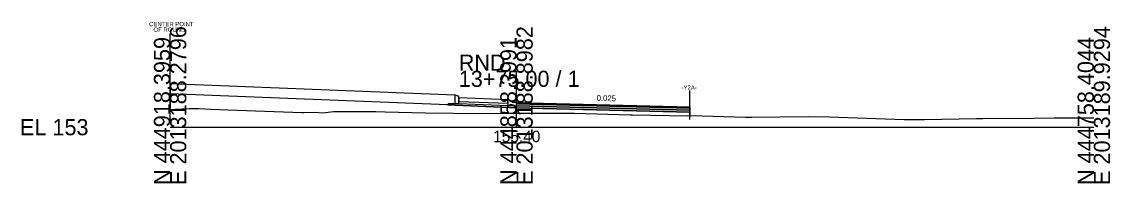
# Model space of a CAD drawing. Extents: x -26 to 163, y -10 to 7518.
# Drawn here: x -25.7 to 162.8, y 7490.3 to 7518.2 of the extents above; entities that cross this region are included whole.
import ezdxf

# ---------------------------------------------------------------- set-up
doc = ezdxf.new("R2010")
doc.units = 0
for name, color, linetype in [('Exist Cross Section Cell', 7, 'Continuous'), ('Exist XS Center Line Elevation Label', 7, 'Continuous'), ('Exist XS Ground Line', 7, 'Continuous'), ('Prop CMT Conc Surface', 7, 'Continuous'), ('Prop CMT Concrete Structures', 7, 'Continuous'), ('Prop CMT Pvmt Course 1', 7, 'Continuous'), ('Prop CMT Pvmt Course 1 CG', 7, 'Continuous'), ('Prop CMT Pvmt Course 2', 7, 'Continuous'), ('Prop CMT Pvmt Course 3', 7, 'Continuous'), ('Prop CMT Pvmt Surface', 7, 'Continuous'), ('Prop CMT Shear Line', 7, 'Continuous'), ('Prop CMT Shear Line Text', 7, 'Continuous'), ('Prop CMT Slope Grass', 7, 'Continuous'), ('Prop CMT Subgrade Earthwork', 7, 'Continuous'), ('Prop XS Earthwork Shape', 7, 'Continuous'), ('Prop XS SE Text', 7, 'Continuous')]:
    doc.layers.add(name, color=color, linetype=linetype)

msp = doc.modelspace()

# ---------------------------------------------------------------- linework, layer by layer
at = {"layer": 'Exist Cross Section Cell'}
for p, q in [((60, 7500), (60, 7509.77)), ((0, 7500), (60, 7500)), ((60, 7500), (160, 7500))]:
    msp.add_line(p, q, dxfattribs=at)
at = {"layer": 'Exist XS Ground Line'}
msp.add_lwpolyline([(0, 7503.05), (0.81, 7503.1), (2.09, 7503.18), (3.3, 7503.26), (3.77, 7503.25), (4.96, 7503.24), (7.08, 7503.13), (10.02, 7502.99), (18.03, 7502.71), (22.9, 7502.56), (23.24, 7502.54), (25.03, 7502.58), (26.43, 7502.5), (28.33, 7502.74), (35.65, 7502.69), (37.24, 7502.65), (44.25, 7502.48), (53.81, 7502.38), (58.55, 7502.4), (60, 7502.4), (69.32, 7502.44), (69.67, 7502.44), (70.02, 7502.43), (79.67, 7502.13), (80.12, 7502.13), (89.67, 7501.99), (90.23, 7502.01), (99.67, 7501.76), (100.77, 7501.73), (110.53, 7501.84), (114.13, 7501.77), (127.12, 7501.32), (129.68, 7501.31), (130.65, 7501.31), (139.68, 7501.52), (140.76, 7501.51), (149.68, 7501.56), (153.12, 7501.59), (160, 7501.64)], dxfattribs=at)
at = {"layer": 'Prop CMT Conc Surface'}
for points in [[(50, 7505.24), (49.96, 7505.34), (49.85, 7505.39), (49.34, 7505.58)], [(50, 7505.08), (50, 7505.24)], [(60, 7504.28), (59.25, 7504.3), (59.25, 7504.47), (58.5, 7504.72)]]:
    msp.add_lwpolyline(points, dxfattribs=at)
at = {"layer": 'Prop CMT Concrete Structures'}
for points in [[(50, 7505.24), (49.96, 7505.34), (49.85, 7505.39), (49.34, 7505.58)], [(49.34, 7505.58), (49.34, 7504.08)], [(49.34, 7504.08), (50, 7504.08)], [(50, 7505.08), (50, 7505.24)], [(50, 7504.08), (50, 7505.08)], [(50, 7505.08), (50, 7504.49)], [(58.5, 7504.72), (50, 7505.06)], [(50, 7504.47), (58.5, 7504.13)], [(60, 7504.28), (59.25, 7504.3), (59.25, 7504.47), (58.5, 7504.72)], [(58.5, 7504.72), (58.5, 7503.73)], [(58.5, 7504.13), (58.5, 7504.72)], [(58.5, 7503.73), (60, 7503.7)], [(60, 7503.7), (60, 7504.28)]]:
    msp.add_lwpolyline(points, dxfattribs=at)
at = {"layer": 'Prop CMT Pvmt Course 1'}
for points in [[(60, 7504.28), (90, 7503.53)], [(60, 7504.03), (60, 7504.28)], [(90, 7503.28), (60, 7504.03)], [(90, 7503.53), (90, 7503.28)]]:
    msp.add_lwpolyline(points, dxfattribs=at)
msp.add_lwpolyline([(60, 7504.03), (60, 7504.15), (60, 7504.15), (60, 7504.03)], close=True, dxfattribs=at)
at = {"layer": 'Prop CMT Pvmt Course 1 CG'}
for points in [[(60, 7503.36), (60, 7503.7)], [(90, 7502.61), (90, 7502.94)]]:
    msp.add_lwpolyline(points, dxfattribs=at)
at = {"layer": 'Prop CMT Pvmt Course 2'}
for points in [[(60, 7503.7), (60, 7504.03)], [(60, 7504.03), (90, 7503.28)], [(90, 7502.94), (60, 7503.7)], [(90, 7503.28), (90, 7502.94)]]:
    msp.add_lwpolyline(points, dxfattribs=at)
at = {"layer": 'Prop CMT Pvmt Course 3'}
for points in [[(50, 7504.08), (58.5, 7503.73)], [(60, 7503.7), (90, 7502.94)], [(60, 7503.36), (60, 7503.7)], [(90, 7502.61), (60, 7503.36)], [(90, 7502.94), (90, 7502.61)]]:
    msp.add_lwpolyline(points, dxfattribs=at)
at = {"layer": 'Prop CMT Pvmt Surface'}
msp.add_lwpolyline([(60, 7504.28), (90, 7503.53)], dxfattribs=at)
at = {"layer": 'Prop CMT Shear Line'}
for p, q in [((0, 7501.22), (0, 7516.22)), ((90, 7501.35), (90, 7506.37))]:
    msp.add_line(p, q, dxfattribs=at)
at = {"layer": 'Prop CMT Slope Grass'}
for p, q in [((49.34, 7505.56), (0, 7507.53)), ((48.06, 7503.84), (0, 7505.76))]:
    msp.add_line(p, q, dxfattribs=at)
at = {"layer": 'Prop CMT Subgrade Earthwork'}
for p, q in [((0, 7507.53), (0, 7503.05)), ((48.34, 7504.12), (48.06, 7503.84)), ((90, 7503.53), (90, 7502.61)), ((90, 7502.61), (90, 7502))]:
    msp.add_line(p, q, dxfattribs=at)
for points in [[(48.06, 7503.84), (60, 7503.36)], [(48.34, 7504.12), (49.34, 7504.08)], [(60, 7503.36), (90, 7502.61)]]:
    msp.add_lwpolyline(points, dxfattribs=at)
at = {"layer": 'Prop XS Earthwork Shape'}
msp.add_lwpolyline([(7.08, 7503.13), (10.02, 7502.99), (18.03, 7502.71), (22.9, 7502.56), (23.24, 7502.54), (25.03, 7502.58), (26.43, 7502.5), (28.33, 7502.74), (35.65, 7502.69), (37.24, 7502.65), (44.25, 7502.48), (53.81, 7502.38), (58.55, 7502.4), (60, 7502.4), (69.32, 7502.44), (69.67, 7502.44), (70.02, 7502.43), (79.67, 7502.13), (80.12, 7502.13), (89.67, 7501.99), (90, 7502), (90, 7502.61), (60, 7503.36), (48.06, 7503.84), (0, 7505.76), (0, 7503.05), (0.81, 7503.1), (2.09, 7503.18), (3.3, 7503.26), (3.77, 7503.25), (4.96, 7503.24)], close=True, dxfattribs=at)

# ---------------------------------------------------------------- texts
at = {"layer": 'Exist Cross Section Cell'}
for s, p in [('E 2013188.2796', (2.8, 7490)), ('E 2013188.8982', (62.8, 7490)), ('E 2013189.9294', (162.8, 7490)), ('N 444918.3959', (0, 7490)), ('N 444858.3991', (60, 7490)), ('N 444758.4044', (160, 7490))]:
    msp.add_text(s, height=2.8, rotation=90, dxfattribs=at).set_placement(p)
for s, p in [('RND', (50, 7509.77)), ('13+75.00 / 1', (50, 7506.97)), ('EL 153', (-26, 7498.6))]:
    msp.add_text(s, height=2.8, dxfattribs=at).set_placement(p)
at = {"layer": 'Exist XS Center Line Elevation Label'}
msp.add_text('155.40', height=2, dxfattribs=at).set_placement((55.95, 7497.4))
at = {"layer": 'Prop CMT Shear Line Text'}
for s, p in [('CENTER POINT', (-3.64, 7517.47)), ('OF ROUND', (-2.88, 7516.5)), ('-Y2A-', (88.59, 7506.48))]:
    msp.add_text(s, height=0.75, dxfattribs=at).set_placement(p)
at = {"layer": 'Prop XS SE Text'}
msp.add_text('0.025', height=1, rotation=358.5613, dxfattribs=at).set_placement((73.87, 7504.56))

doc.saveas('drawing.dxf')
